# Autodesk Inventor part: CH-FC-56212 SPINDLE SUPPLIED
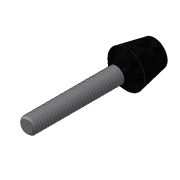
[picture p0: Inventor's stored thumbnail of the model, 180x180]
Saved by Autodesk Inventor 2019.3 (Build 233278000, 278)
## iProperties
Created: 2012-09
Part Number: CH-FC-56212 SPINDLE SUPPLIED
Material: Ogólny
Document SubType Name: Modeling
Designer: CADENGINEERING4
Density: 1 g/cm^3
Appearance: Domyślna
Author: CADENGINEERING4
Revision Number: ÈÎºÎ
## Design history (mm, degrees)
feature "Ðý×ª2"
node "Bryła1"
